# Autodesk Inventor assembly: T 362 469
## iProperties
Company: Mayer & Müller AG Schaltgeräte
Created: 2006-10
Part Number: T 362 469
Document SubType Name: Assembly
Designer: I.Baliuc
Description: Isolator
Mass: 798.776 g
Surface Area: 1411.18 cm^2
Volume: 649.743 cm^3
Density: 1.22937 g/cm^3
Author: T.Messerschmitt
Revision Number: 362469
